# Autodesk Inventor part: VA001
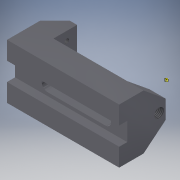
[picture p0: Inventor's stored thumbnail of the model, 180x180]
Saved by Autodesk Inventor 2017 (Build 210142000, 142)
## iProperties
Manager: P MOLLOY
Company: NUIG
Shininess: 64.0
Length Units: 11269
Angle Units: 11279
Time Units: 11290
Mass Units: 11283
Length Display Precision: 3
Angle Display Precision: 2
Compacted: True
Part Number: VA001
Document SubType Name: Modeling
Created: 2004-12
Designer: warren davies
Manufacturer: Standard
Standards Organization: Custom
Project: TRAINING VICE ASSY
Material: Steel, High Strength Low Alloy
Density: 7.84 g/cm^3
Appearance: Metal-Steel (Polished)
Density: 0.0
Volumn: 0.0
Area: 0.0
PropertySet Name: Model Information
Control State: 0
Master: False
Checked Out: False
quality engineer: john hannon
Title: BASE
Subject: VICE ASSEMBLY
Author: warren davies
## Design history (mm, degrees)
sketch "Sketch1"
  geometry: L1 (0, 0)-(-152, 0); L2 (-152, 0)-(-152, 45); L3 (-152, 45)-(-132, 65); L4 (-132, 65)-(-122, 65); L5 (-122, 65)-(-122, 33); L6 (-122, 33)-(-22, 33); L7 (-22, 33)-(-22, 63); L8 (-22, 63)-(0, 63); L9 (0, 63)-(0, 0)
  constraints: 18 end point, 6 parallel, 1 horizontal, 1 perpendicular, 1 other
  dimensions: "d0" = 152 distance of L1.start L1.end; "d1" = 63 distance between parallel lines of L1 L8; "d2" = 22 distance of L7.end L8.end; "d3" = 65 distance between parallel lines of L1 L4; "d4" = 30 distance between parallel lines of L5 L2; "d5" = 10 distance of L3.end L4.end; "d6" = 45 deg angle of L3 L4; "d7" = 33 distance between parallel lines of L1 L6
extrude "Extrusion1" new body sketch "Sketch1" distance "d8" = 74; taper "d9" = 0 deg
sketch "Sketch2"
  geometry: L1 (-74, 63)-(-74, 0) reference; L2 (0, 63)-(0, 0) reference; L3 (0, 63)-(-74, 63) reference; L4 (-74, 33)-(-49.5, 63); L5 (0, 63)-(-74, 63) reference; L6 (-24.5, 63)-(0, 33)
  constraints: 4 end point, 4 point on line
  dimensions: "d12" = 30 vertical distance of L4.start L4.end; "d13" = 24.5 distance of L4.end L1.start; "d14" = 24.5 distance of L2.start L6.start; "d15" = 30 distance of L6.end L2.start
extrude "ANGLEDEND" cut sketch "Sketch2" distance "d16" = 22; taper "d17" = 0 deg
sketch "Sketch3"
  geometry: L1 (100, 74)-(100, 0) reference; L2 (0, 74)-(100, 74) reference; L3 (14, 45)-(92, 45); L4 (92, 29)-(14, 29); A1 r 8 centre (14, 37) between (14, 45) and (14, 29); A2 r 8 centre (92, 37) between (92, 29) and (92, 45)
  constraints: 4 end point, 4 point on circle, 2 centre point, 1 equal radius, 1 horizontal, 1 parallel
  dimensions: "d18" = 16 distance between parallel lines of L4 L3; "d19" = 78 distance of A2.centre A1.centre; "d20" = 8 radius of A1; "d21" = 8 distance from line of L1 A2.centre; "d22" = 37 distance from line of L2 A2.centre
extrude "SLOT" cut sketch "Sketch3" stored distance "d23" = 22; taper "d24" = 0 deg
sketch "Sketch4"
  geometry: L1 (49.5, 63)-(24.5, 63) reference; L2 (74, 0)-(0, 0) reference; L3 (37, 63)-(37, 0); L4 (74, 0)-(0, 0) reference; L5 (24.5, 0)-(24.5, 11); L6 (29, 33)-(29, 0) reference; L7 (24.5, 11)-(49.5, 11); L8 (49.5, 11)-(49.5, 0); 1 further point
  constraints: 8 end point, 3 midpoint, 3 point on line, 2 perpendicular, 1 parallel
  dimensions: "d25" = 25 distance of L5.end L7.end; "d26" = 11 distance of L7.end L8.end
extrude "RECTANGSLOT" cut sketch "Sketch4" stored distance "d27" = 22; taper "d28" = 0 deg
sketch "Sketch5"
  geometry: L1 (49.5, 0)-(74, 0) reference; L2 (74, 0)-(74, 45) reference; C1 r 8 at (37, 25)
  constraints: 1 centre point
  dimensions: "d29" = 16 diameter of C1; "d30" = 37 distance from line of L2 C1.centre; "d31" = 25 distance from line of L1 C1.centre
extrude "SAFTEYHOLE" cut sketch "Sketch5" distance "d32" = 13; taper "d33" = 0 deg
sketch "Sketch6"
  geometry: L1 (-74, 32)-(-74, 0) reference; L2 (0, 32)-(-74, 32) reference; C1 r 3 at (-12, 18); C2 r 3 at (-62, 18)
  constraints: 2 centre point, 1 equal radius, 1 horizontal alignment
  dimensions: "d35" = 6 diameter of C1; "d36" = 50 distance of C1.centre C2.centre; "d37" = 12 distance from line of L1 C2.centre; "d38" = 14 distance from line of C2.centre L2
extrude "FIXING DRILL" cut sketch "Sketch6" stored distance "d39" = 13; taper "d40" = 0 deg
workplane "Work Plane1"
sketch "Sketch8"
  geometry: L1 (-24.5, 63)-(-49.5, 63) reference; C1 r 6.5 at (-37, 54); 1 further point
  constraints: 1 centre point, 1 midpoint, 1 vertical alignment
  dimensions: "d44" = 9 distance from line of L1 C1.centre; "d45" = 13 diameter of C1
extrude "HANDLE HOLE" cut sketch "Sketch8" distance "d46" = 22; taper "d47" = 0 deg
thread "Thread1" dims "d48" = 10, "d49" = 0
thread "Thread2" dims "d53" = 10, "d54" = 0
thread "Thread3" dims "d57" = 10, "d58" = 0
thread "Thread4" dims "d59" = 10, "d60" = 0
body "Solid1"
